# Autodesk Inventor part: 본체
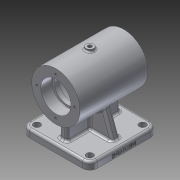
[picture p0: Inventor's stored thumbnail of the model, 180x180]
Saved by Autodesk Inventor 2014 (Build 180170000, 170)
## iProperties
Created: 2019-06
Part Number: 본체
Material: 알루미늄 6061
Document SubType Name: Modeling
Designer: OA55
Density: 2.71 g/cm^3
Appearance: 알루미늄 - 평지
Author: OA55
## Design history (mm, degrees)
sketch "스케치1"
  geometry: C1 r 32 at (0, 0); 1 further point
  constraints: 1 centre point, 1 coincident
  dimensions: "d0" = 64 diameter of C1
extrude "돌출1" new body sketch "스케치1" stored distance "d1" = 90; taper "d2" = 0 deg
node "작업 평면1"
sketch "스케치2"
  geometry: C1 r 25 at (0, 0); 1 further point
  constraints: 1 centre point, 1 coincident
  dimensions: "d3" = 50 diameter of C1
extrude "돌출2" cut sketch "스케치2" stored distance "d4" = 48; taper "d5" = 0 deg
sketch "스케치3"
  geometry: C1 r 32 at (0, 0) reference; C2 r 20 at (0, 0)
  constraints: 1 centre point, 1 coincident
  dimensions: "d6" = 40 diameter of C2
extrude "돌출3" cut sketch "스케치3" distance "d7" = 15; taper "d8" = 0 deg
node "작업 평면2"
sketch "스케치4"
  geometry: C1 r 20 at (0, 0) reference; C2 r 17 at (0, 0)
  constraints: 1 centre point, 1 coincident
  dimensions: "d9" = 34 diameter of C2
extrude "돌출4" cut sketch "스케치4" stored distance "d10" = 15; taper "d11" = 0 deg
sketch "스케치5" dims "d12" = 50
  geometry: L1 (0, 0)-(0, 25); C1 r 32 at (0, 0) reference; 1 further point
  constraints: 2 coincident, 2 end point, 1 vertical, 1 vertical alignment, 2 other
hole "구멍1" sketch "스케치5" at (0, 25) diameter "d13" = 3.242; stored, may be unused: countersink angle "d17" = 90 deg, drill point angle "d19" = 118 deg; dims "d14" = 7, "d15" = 4, "d16" = 2, "d18" = 9
node "작업 평면3"
node "작업 평면4"
sketch "스케치6"
  geometry: C1 r 5 at (0, 0); 1 further point
  constraints: 1 centre point, 1 coincident
  dimensions: "d24" = 10 diameter of C1
extrude "돌출5" join sketch "스케치6" stored distance "d25" = 10; taper "d26" = 0 deg
sketch "스케치7"
  geometry: 2 further points
  constraints: 1 coincident
hole "구멍2" sketch "스케치7" at (0, 0) diameter "d27" = 4.917; stored, may be unused: countersink angle "d31" = 90 deg, drill point angle "d33" = 118 deg; dims "d28" = 10, "d29" = 4, "d30" = 2, "d32" = 20
fillet "모깎기1" dims "d34" = 2
node "작업 평면6"
sketch "스케치8"
  geometry: L1 (0, 0)-(0, 45); L2 (0, 45)-(-45, 45); L3 (-45, 45)-(-45, -45); L4 (-45, -45)-(45, -45); L5 (45, -45)-(45, 45); L6 (45, 45)-(0, 45); 1 further point
  constraints: 12 end point, 3 vertical, 2 horizontal, 1 coincident
  dimensions: "d37" = 45 distance of L1.start L1.end; "d38" = 45 distance of L1.end L2.end; "d39" = 90 distance of L2.end L3.end; "d40" = 90 distance of L3.end L4.end; "d41" = 90 distance of L4.end L5.end
extrude "돌출6" join sketch "스케치8" distance "d42" = 10; taper "d43" = 0 deg
fillet "모깎기2" dims "d44" = 10
sketch "스케치9"
  geometry: C1 r 4.5 at (-35, 35); C2 r 4.5 at (35, 35); C3 r 4.5 at (-35, -35); C4 r 4.5 at (35, -35); A1 r 10 centre (-35, 35) between (-35, 45) and (-45, 35) reference; A2 r 10 centre (-35, -35) between (-45, -35) and (-35, -45) reference; A3 r 10 centre (35, -35) between (35, -45) and (45, -35) reference; A4 r 10 centre (35, 35) between (45, 35) and (35, 45) reference; 1 further point
  constraints: 4 centre point, 4 coincident
  dimensions: "d45" = 9 diameter of C1; "d46" = 9 diameter of C2; "d47" = 9 diameter of C3; "d48" = 9 diameter of C4
fillet "모깎기3" dims "d51" = 3
fillet "모깎기4" dims "d52" = 0.6
sketch "스케치11"
  geometry: L1 (35, -45)-(-35, -45) reference; L2 (45, 35)-(45, -35) reference; L3 (-35, 45)-(35, 45) reference; L4 (0, 0)-(0, 40); L5 (0, 40)-(-26.34, 40); L6 (-40, 26.34)-(-40, -26.34); L7 (-26.34, -40)-(26.34, -40); L8 (40, -26.34)-(40, 26.34); L9 (26.34, 40)-(0, 40); A1 r 10 centre (-35, -35) between (-45, -35) and (-35, -45) reference; A2 r 10 centre (35, -35) between (35, -45) and (45, -35) reference; A3 r 10 centre (35, 35) between (45, 35) and (35, 45) reference; A4 r 10 centre (-35, 35) between (-35, 45) and (-45, 35) reference; A5 r 10 centre (35, 35) between (26.34, 40) and (40, 26.34); A6 r 10 centre (35, -35) between (40, -26.34) and (26.34, -40); A7 r 10 centre (-35, -35) between (-26.34, -40) and (-40, -26.34); A8 r 10 centre (-35, 35) between (-40, 26.34) and (-26.34, 40)
  constraints: 16 end point, 8 point on circle, 4 centre point, 4 coincident, 3 vertical, 2 horizontal
  dimensions: "d53" = 40 distance of L4.start L4.end; "d62" = 10 radius of A8; "d63" = 10 radius of A5; "d66" = 52.67949 distance of L8.start L8.end; "d67" = 52.67949 distance of L7.start L7.end; "d68" = 52.67949 distance of L6.start L6.end; "d69" = 26.33975 distance of L9.start L4.end; "d70" = 10 radius of A6; "d71" = 10 radius of A7
extrude "돌출8" cut sketch "스케치11" distance "d72" = 5; taper "d73" = 0 deg
fillet "모깎기5" dims "d74" = 3
extrude "돌출9" cut sketch "스케치9" distance "d75" = 10; taper "d76" = 0 deg
fillet "모깎기6" dims "d77" = 3
sketch "스케치12"
  geometry: L1 (0, 0)-(0, -35); L2 (0, 0)-(0, 35); L3 (0, 35)-(5, 35); L4 (5, 35)-(5, -35); L5 (5, -35)-(-5, -35); L6 (-5, -35)-(-5, 35); L7 (-5, 35)-(0, 35)
  constraints: 14 end point, 4 vertical, 2 horizontal
  dimensions: "d78" = 35 distance of L1.start L1.end; "d79" = 35 distance of L1.start L2.end; "d80" = 5 distance of L2.end L3.end; "d81" = 70 distance of L3.end L4.end; "d82" = 10 distance of L4.end L5.end; "d83" = 70 distance of L5.end L6.end
extrude "돌출10" join sketch "스케치12" stored distance "d84" = 10; taper "d85" = 0 deg
node "작업 평면7"
sketch "스케치13"
  geometry: L1 (40, -65)-(40, -60) reference; L2 (40, -60)-(-40, -60) reference; L3 (-40, -60)-(-40, -65) reference; L4 (-40, -65)-(-45, -65) reference; L5 (-45, -65)-(-45, -58) reference; L6 (-42, -55)-(-5, -55) reference; L7 (-5, -55)-(-5, -31.607) reference; L8 (-5, 33.272)-(-5, 35) reference; L9 (-5, 35)-(-2.458, 35) reference; L10 (-2.458, 35)-(-2.458, 24.879) reference; L11 (2.458, 24.879)-(2.458, 35) reference; L12 (2.458, 35)-(5, 35) reference; L13 (5, 35)-(5, 33.272) reference; L14 (5, -31.607)-(5, -55) reference; L15 (5, -55)-(42, -55) reference; L16 (45, -58)-(45, -65) reference; L17 (45, -65)-(40, -65) reference; L18 (-35, -55)-(-23.058, -22.189); L19 (35, -55)-(23.058, -22.189); A1 r 3 centre (-42, -58) between (-42, -55) and (-45, -58) reference; A2 r 32 centre (0, 0) between (-6.588, 31.314) and (-5, -31.607) reference; A3 r 25 centre (0, 0) between (-2.458, 24.879) and (2.458, 24.879) reference; A4 r 32 centre (0, 0) between (5, -31.607) and (6.588, 31.314) reference; A5 r 3 centre (42, -58) between (45, -58) and (42, -55) reference; 1 further point
  constraints: 4 end point, 2 point on circle, 2 point on line, 2 other
  dimensions: "d87" = 10 distance from line of L18.start L5; "d88" = 10 distance from line of L16 L19.start; "d89" = 110 deg angle of L18 L6; "d90" = 110 deg angle of L15 L19
  node "절단 모서리 투영2"
feature "리브1" dims "d91" = 1, "d92" = 10, "d93" = 0, "d94" = 0, "d95" = 1, "d96" = 1
feature "리브2" dims "d97" = 1, "d98" = 10, "d99" = 0, "d100" = 0, "d101" = 1, "d102" = 1
fillet "모깎기7" dims "d103" = 3
fillet "모깎기8" dims "d104" = 3
fillet "모깎기9" dims "d105" = 3
sketch "스케치14"
  geometry: L1 (0, 0)-(70, 0) reference; L2 (-10, 7)-(-10, 0) reference; 2 further points
  constraints: 1 other
  dimensions: "d106" = 4 distance from line of L1 point (35, 4); "d107" = 45 distance from line of point (35, 4) L2
feature "엠보싱1" sketch "스케치14" dims "d0" = 64, "d108" = 0.5, "d109" = 0
node "솔리드1"
mirror "대칭1"
pattern_circular "원형 패턴1" dims angle "d21" = 360 deg
mirror "대칭2"
other parameters: "d23" = 35, "d36" = -65, "d86" = 0
